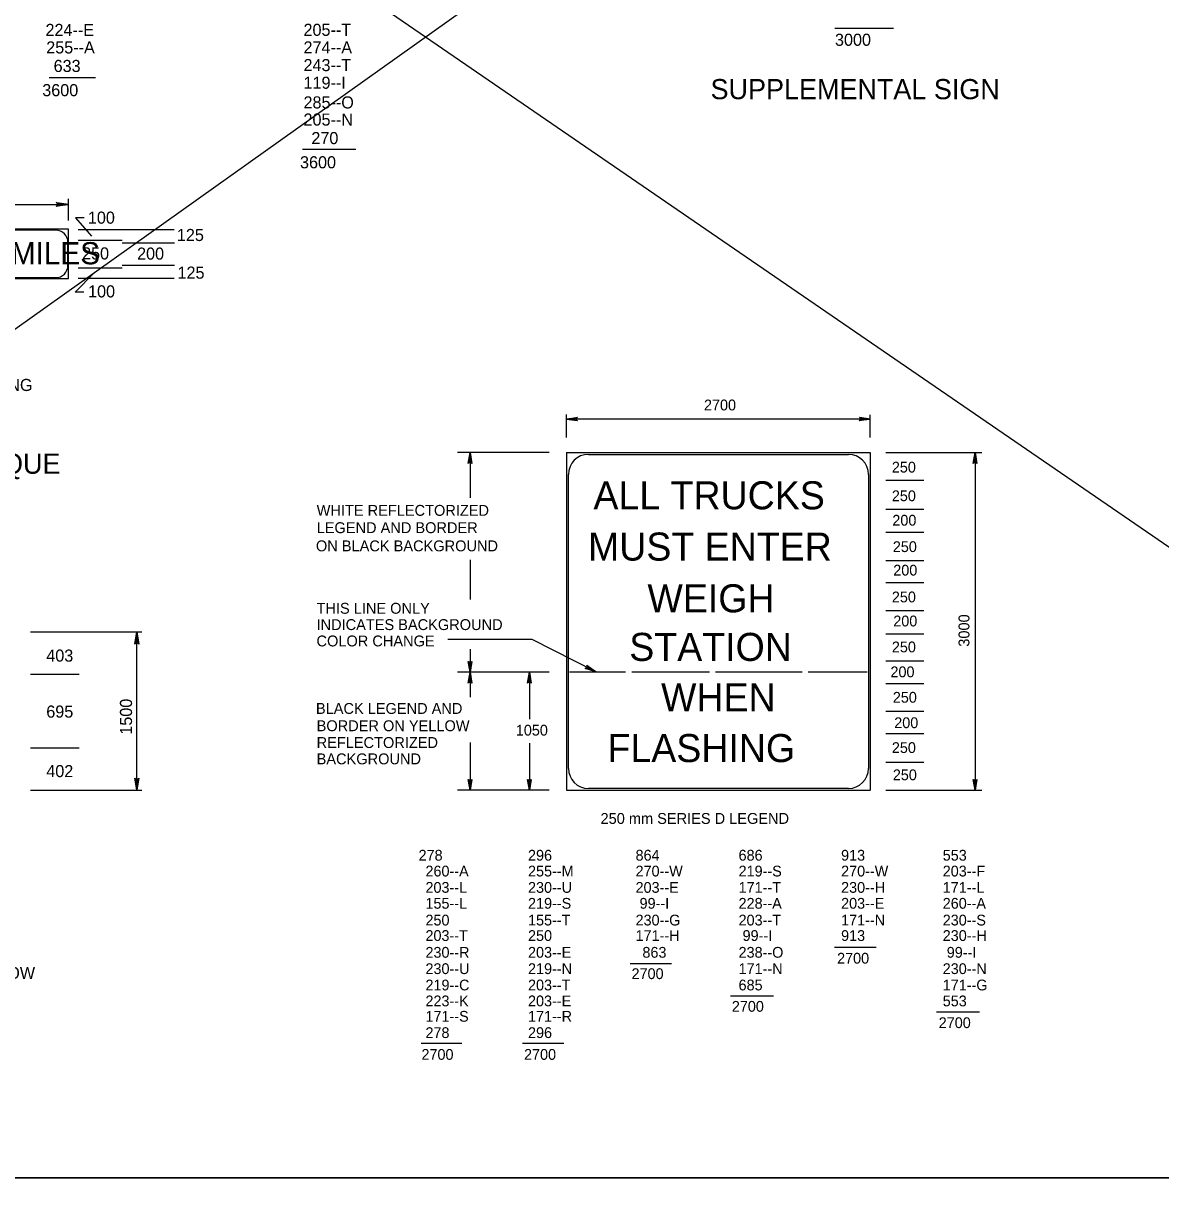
# Model space of a CAD drawing. Extents: x 649604 to 650509, y 298458 to 299646.
# Drawn here: x 649924.8 to 650206.9, y 299064.9 to 299352.8 of the extents above; entities that cross this region are included whole.
import ezdxf

# ---------------------------------------------------------------- set-up
doc = ezdxf.new("R2010")
doc.units = 0
for name, color, linetype in [('1', 7, 'Continuous'), ('2', 7, 'Continuous'), ('3', 7, 'Continuous')]:
    doc.layers.add(name, color=color, linetype=linetype)

# ---------------------------------------------------------------- blocks, each defined once
blk = doc.blocks.new('RARROW')
at = {"layer": '3'}
blk.add_lwpolyline([(-2.2695, 0.285), (-2.184875, 0.12075), (0, 0), (-2.2695, 0.285), (-2.38575, 0.384625), (0, 0), (-2.183125, -0.108), (-2.262875, -0.2705), (0, 0), (-2.38575, -0.379125), (-2.262875, -0.2705)], dxfattribs=at)

msp = doc.modelspace()

# ---------------------------------------------------------------- linework, layer by layer
at = {"layer": '1'}
for p, q in [((650430.31, 299066.63), (649644.31, 299066.63)), ((649644.31, 299066.63), (650230.31, 299066.63))]:
    msp.add_line(p, q, dxfattribs=at)
at = {"layer": '2'}
for p, q in [((650429.28, 299637.34), (649624.76, 299064.89)), ((649618.13, 299628.5), (650435.92, 299067.1)), ((650126.06, 299351.63), (650140.56, 299351.63)), ((649931.26, 299339.35), (649942.76, 299339.35)), ((649994.04, 299321.6), (650007.29, 299321.6)), ((649936.02, 299303.88), (649936.02, 299309.27)), ((649848.15, 299307.89), (649936.02, 299307.89)), ((649936.02, 299301.78), (649848.15, 299301.78)), ((649936.02, 299289.5), (649936.02, 299301.78)), ((649938.4, 299301.68), (649962.25, 299301.68)), ((649938.4, 299299.01), (649949.33, 299299.01)), ((649949.33, 299298.35), (649962.32, 299298.35)), ((649938.4, 299292.18), (649949.33, 299292.18)), ((649949.33, 299292.85), (649962.32, 299292.85)), ((649848.15, 299289.5), (649936.02, 299289.5)), ((649938.4, 299289.6), (649962.25, 299289.6)), ((650059.55, 299250.15), (650059.55, 299255.83)), ((650134.82, 299254.71), (650059.55, 299254.71)), ((650134.82, 299250.15), (650134.82, 299255.72)), ((650055.23, 299246.38), (650032.48, 299246.38)), ((650035.59, 299246.38), (650035.59, 299235.13)), ((650059.55, 299246.38), (650134.82, 299246.38)), ((650059.55, 299246.38), (650059.55, 299162.68)), ((650064.95, 299245.93), (650129.42, 299245.93)), ((650134.82, 299246.38), (650134.82, 299162.68)), ((650138.72, 299246.38), (650162.49, 299246.38)), ((650160.8, 299246.38), (650160.8, 299162.68)), ((650060, 299168.08), (650060, 299240.98)), ((650134.37, 299240.98), (650134.37, 299168.08)), ((650138.72, 299239.52), (650148.1, 299239.52)), ((650138.72, 299232.32), (650148.1, 299232.32)), ((650138.72, 299226.69), (650148.1, 299226.69)), ((650035.59, 299219.76), (650035.59, 299209.95)), ((650138.72, 299219.61), (650148.1, 299219.61)), ((650138.72, 299214.21), (650148.1, 299214.21)), ((650138.72, 299207.23), (650148.1, 299207.23)), ((649926.6, 299201.93), (649954.23, 299201.93)), ((649952.98, 299162.68), (649952.98, 299201.93)), ((650051, 299200.03), (650030.1, 299200.03)), ((650066.75, 299192.04), (650051, 299200.03)), ((650138.72, 299201.49), (650148.1, 299201.49)), ((650035.59, 299197.65), (650035.59, 299191.93)), ((650138.72, 299194.74), (650148.1, 299194.74)), ((649926.6, 299191.43), (649938.66, 299191.43)), ((650055.23, 299191.93), (650032.48, 299191.93)), ((650035.59, 299191.93), (650035.59, 299185.74)), ((650050.32, 299191.93), (650050.32, 299180.34)), ((650074.18, 299191.93), (650060.23, 299191.93)), ((650094.99, 299191.93), (650075.75, 299191.93)), ((650117.94, 299191.93), (650096.45, 299191.93)), ((650134.03, 299191.93), (650119.4, 299191.93)), ((650138.72, 299189.12), (650148.1, 299189.12)), ((650138.72, 299182.26), (650148.1, 299182.26)), ((650138.72, 299176.74), (650148.1, 299176.74)), ((649926.6, 299173.18), (649938.66, 299173.18)), ((650035.59, 299174.49), (650035.59, 299162.68)), ((650050.32, 299174.38), (650050.32, 299162.68)), ((650138.72, 299169.66), (650148.1, 299169.66)), ((649926.6, 299162.68), (649954.23, 299162.68)), ((650055.23, 299162.68), (650032.48, 299162.68)), ((650059.55, 299162.68), (650134.82, 299162.68)), ((650129.42, 299163.13), (650064.95, 299163.13)), ((650138.72, 299162.68), (650162.49, 299162.68)), ((650125.93, 299123.76), (650136.28, 299123.76)), ((650075.3, 299119.71), (650085.54, 299119.71)), ((650100.17, 299111.72), (650110.85, 299111.72)), ((650151.24, 299107.78), (650161.93, 299107.78)), ((650023.44, 299100.02), (650033.57, 299100.02)), ((650048.64, 299100.02), (650058.88, 299100.02))]:
    msp.add_line(p, q, dxfattribs=at)
for points in [[(649939.94, 299304.57), (649937.75, 299304.57), (649941.78, 299300.04)], [(649932.9, 299301.53), (649851.4, 299301.53)], [(649935.9, 299292.75), (649935.9, 299298.53)], [(649939.84, 299286.15), (649937.7, 299286.15), (649942.52, 299291.03)], [(649851.4, 299289.75), (649932.9, 299289.75)]]:
    msp.add_lwpolyline(points, dxfattribs=at)
for centre, radius, start, end in [((649932.9, 299298.53), 3, 0, 90), ((649932.9, 299292.75), 3, 270, 0), ((650064.95, 299240.98), 4.95, 90, 180), ((650129.42, 299240.98), 4.95, 0, 90), ((650064.95, 299168.08), 4.95, 180, 270), ((650129.42, 299168.08), 4.95, 270, 0)]:
    msp.add_arc(centre, radius, start, end, dxfattribs=at)

# ---------------------------------------------------------------- block references
for p, xscale, yscale in [((649936.02, 299307.89), 1.2574347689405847, 1.3092961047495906), ((650134.82, 299254.71), 1.1316912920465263, 1.1783664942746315)]:
    msp.add_blockref('RARROW', p, dxfattribs=dict(at, xscale=xscale, yscale=yscale))
for p, xscale, yscale, rotation in [((650059.55, 299254.71), 1.1316912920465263, 1.1783664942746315, 180), ((650035.59, 299246.38), 1.1316912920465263, 1.1783664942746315, 89.99999999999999), ((650160.8, 299246.38), 1.1316912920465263, 1.1783664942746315, 89.99999999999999), ((649952.98, 299201.93), 1.2574347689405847, 1.3092961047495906, 89.99999999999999), ((650035.59, 299191.93), 1.1316912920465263, 1.1783664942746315, -90.00000000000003), ((650066.75, 299192.04), 1.131691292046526, 1.1783664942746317, -26.73304276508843), ((650035.59, 299191.93), 1.1316912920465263, 1.1783664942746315, 89.99999999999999), ((650050.32, 299191.93), 1.1316912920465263, 1.1783664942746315, 89.99999999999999), ((649952.98, 299162.68), 1.2574347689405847, 1.3092961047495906, -90.00000000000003), ((650035.59, 299162.68), 1.1316912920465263, 1.1783664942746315, -90.00000000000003), ((650050.32, 299162.68), 1.1316912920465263, 1.1783664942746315, -90.00000000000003), ((650160.8, 299162.68), 1.1316912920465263, 1.1783664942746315, -90.00000000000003)]:
    msp.add_blockref('RARROW', p, dxfattribs=dict(at, xscale=xscale, yscale=yscale, rotation=rotation))

# ---------------------------------------------------------------- texts
for s, height, p in [(' 224--E', 3, (649929.22, 299349.66)), (' 205--T', 3, (649993.19, 299349.69)), ('3000   ', 3, (650126.08, 299347.22)), (' 255--A', 3, (649929.4, 299345.32)), (' 274--A', 3, (649993.19, 299345.32)), ('633', 3, (649932.35, 299340.73)), (' 243--T', 3, (649993.19, 299340.94)), ('3600', 3, (649929.53, 299334.73)), (' 119--I', 3, (649993.2, 299336.57)), ('SUPPLEMENTAL SIGN', 5, (650095.23, 299333.98)), (' 285--O', 3, (649993.19, 299331.69)), (' 205--N', 3, (649993.19, 299327.44)), ('270', 3, (649996.25, 299322.85)), ('3600', 3, (649993.44, 299316.85)), ('100', 3, (649940.84, 299303.12)), ('125', 3, (649962.91, 299298.83)), ('NEXT REST AREA    MILES', 5.5, (649850.25, 299293.05)), ('250', 3, (649939.4, 299294.26)), ('200', 3, (649953.04, 299294.21)), ('125', 3, (649963.06, 299289.49)), ('100', 3, (649940.89, 299284.85)), ('30% REDUCED SPACING', 3, (649878.97, 299261.65)), ('2700', 2.67, (650093.6, 299256.85)), ('SUPPLEMENTAL PLAQUE', 5, (649851.56, 299241.14)), ('250', 2.67, (650140.18, 299241.44)), ('ALL TRUCKS', 6.955, (650066.19, 299232.32)), ('250', 2.67, (650140.18, 299234.34)), ('WHITE REFLECTORIZED', 2.7, (649997.57, 299230.71)), ('200', 2.67, (650140.3, 299228.28)), ('LEGEND AND BORDER', 2.7, (649997.57, 299226.42)), ('ON BLACK BACKGROUND', 2.7, (649997.39, 299221.91)), ('MUST ENTER', 6.955, (650064.84, 299219.61)), ('250', 2.67, (650140.42, 299221.73)), ('200', 2.67, (650140.53, 299215.9)), ('WEIGH', 6.955, (650079.58, 299206.78)), ('250', 2.67, (650140.18, 299209.26)), ('THIS LINE ONLY', 2.7, (649997.53, 299206.44)), ('INDICATES BACKGROUND', 2.7, (649997.53, 299202.39)), ('200', 2.67, (650140.53, 299203.3)), ('STATION', 6.955, (650075.08, 299194.74)), ('COLOR CHANGE', 2.7, (649997.53, 299198.34)), ('250', 2.67, (650140.18, 299196.87)), ('403', 3, (649930.53, 299194.56)), ('200', 2.67, (650139.83, 299190.7)), ('WHEN', 6.955, (650082.95, 299182.26)), ('BLACK LEGEND AND', 2.7, (649997.39, 299181.61)), ('250', 2.67, (650140.42, 299184.39)), ('695', 3, (649930.53, 299180.68)), ('BORDER ON YELLOW', 2.7, (649997.56, 299177.32)), ('1050', 2.67, (650046.95, 299176.24)), ('200', 2.67, (650140.77, 299178.09)), ('REFLECTORIZED ', 2.7, (649997.56, 299173.16)), ('FLASHING', 6.955, (650069.68, 299169.66)), ('250', 2.67, (650140.18, 299171.92)), ('BACKGROUND', 2.7, (649997.56, 299169.11)), ('402', 3, (649930.53, 299165.93)), ('250', 2.67, (650140.42, 299165.17)), ('250 mm SERIES D LEGEND', 2.7, (650067.95, 299154.34)), ('  278    ', 2.67, (650020.85, 299145.24)), (' 296   ', 2.67, (650048.98, 299145.24)), (' 864   ', 2.67, (650075.64, 299145.24)), (' 686   ', 2.67, (650101.18, 299145.24)), (' 913   ', 2.67, (650126.6, 299145.24)), (' 553   ', 2.67, (650151.8, 299145.24)), (' 260--A', 2.67, (650023.55, 299141.31)), (' 255--M', 2.67, (650048.98, 299141.31)), (' 270--W', 2.67, (650075.64, 299141.31)), (' 219--S', 2.67, (650101.18, 299141.31)), (' 270--W', 2.67, (650126.6, 299141.31)), (' 203--F', 2.67, (650151.8, 299141.31)), (' 203--L', 2.67, (650023.55, 299137.26)), (' 230--U', 2.67, (650048.98, 299137.26)), (' 203--E', 2.67, (650075.64, 299137.26)), (' 171--T', 2.67, (650101.18, 299137.26)), (' 230--H', 2.67, (650126.6, 299137.26)), (' 171--L', 2.67, (650151.8, 299137.26)), (' 155--L', 2.67, (650023.55, 299133.32)), (' 219--S', 2.67, (650048.98, 299133.32)), ('  99--I', 2.67, (650075.64, 299133.32)), (' 228--A', 2.67, (650101.18, 299133.32)), (' 203--E', 2.67, (650126.6, 299133.32)), (' 260--A', 2.67, (650151.8, 299133.32)), (' 250   ', 2.67, (650023.55, 299129.16)), (' 155--T', 2.67, (650048.98, 299129.16)), (' 230--G', 2.67, (650075.64, 299129.16)), (' 203--T', 2.67, (650101.18, 299129.16)), (' 171--N', 2.67, (650126.6, 299129.16)), (' 230--S', 2.67, (650151.8, 299129.16)), (' 203--T', 2.67, (650023.55, 299125.33)), (' 250   ', 2.67, (650048.98, 299125.33)), (' 171--H', 2.67, (650075.64, 299125.33)), ('  99--I', 2.67, (650101.18, 299125.33)), (' 913   ', 2.67, (650126.6, 299125.33)), (' 230--H', 2.67, (650151.8, 299125.33)), (' 230--R', 2.67, (650023.55, 299121.17)), (' 203--E', 2.67, (650048.98, 299121.17)), ('863   ', 2.67, (650078.34, 299121.17)), (' 238--O', 2.67, (650101.18, 299121.17)), ('  99--I', 2.67, (650151.8, 299121.17)), ('2700   ', 2.67, (650126.6, 299119.71)), (' 695--ARROW', 3, (649901.9, 299115.9)), (' 230--U', 2.67, (650023.55, 299117.12)), (' 219--N', 2.67, (650048.98, 299117.12)), ('2700   ', 2.67, (650075.64, 299115.88)), (' 171--N', 2.67, (650101.18, 299117.12)), (' 230--N', 2.67, (650151.8, 299117.12)), (' 219--C', 2.67, (650023.55, 299113.07)), (' 203--T', 2.67, (650048.98, 299113.07)), (' 685   ', 2.67, (650101.18, 299113.07)), (' 171--G', 2.67, (650151.8, 299113.07)), (' 223--K', 2.67, (650023.55, 299109.13)), (' 203--E', 2.67, (650048.98, 299109.13)), ('2700 ', 2.67, (650100.5, 299107.78)), (' 553   ', 2.67, (650151.8, 299109.13)), (' 171--S', 2.67, (650023.55, 299105.31)), (' 171--R', 2.67, (650048.98, 299105.31)), (' 278   ', 2.67, (650023.55, 299101.26)), (' 296   ', 2.67, (650048.98, 299101.26)), ('2700   ', 2.67, (650151.8, 299103.73)), ('2700   ', 2.67, (650023.55, 299095.86)), ('2700   ', 2.67, (650048.98, 299095.86))]:
    msp.add_text(s, height=height, dxfattribs=at).set_placement(p)
for s, height, p in [('3000', 2.7, (650159.41, 299198.26)), ('1500', 3, (649951.79, 299176.45))]:
    msp.add_text(s, height=height, rotation=90, dxfattribs=at).set_placement(p)

doc.saveas('drawing.dxf')
